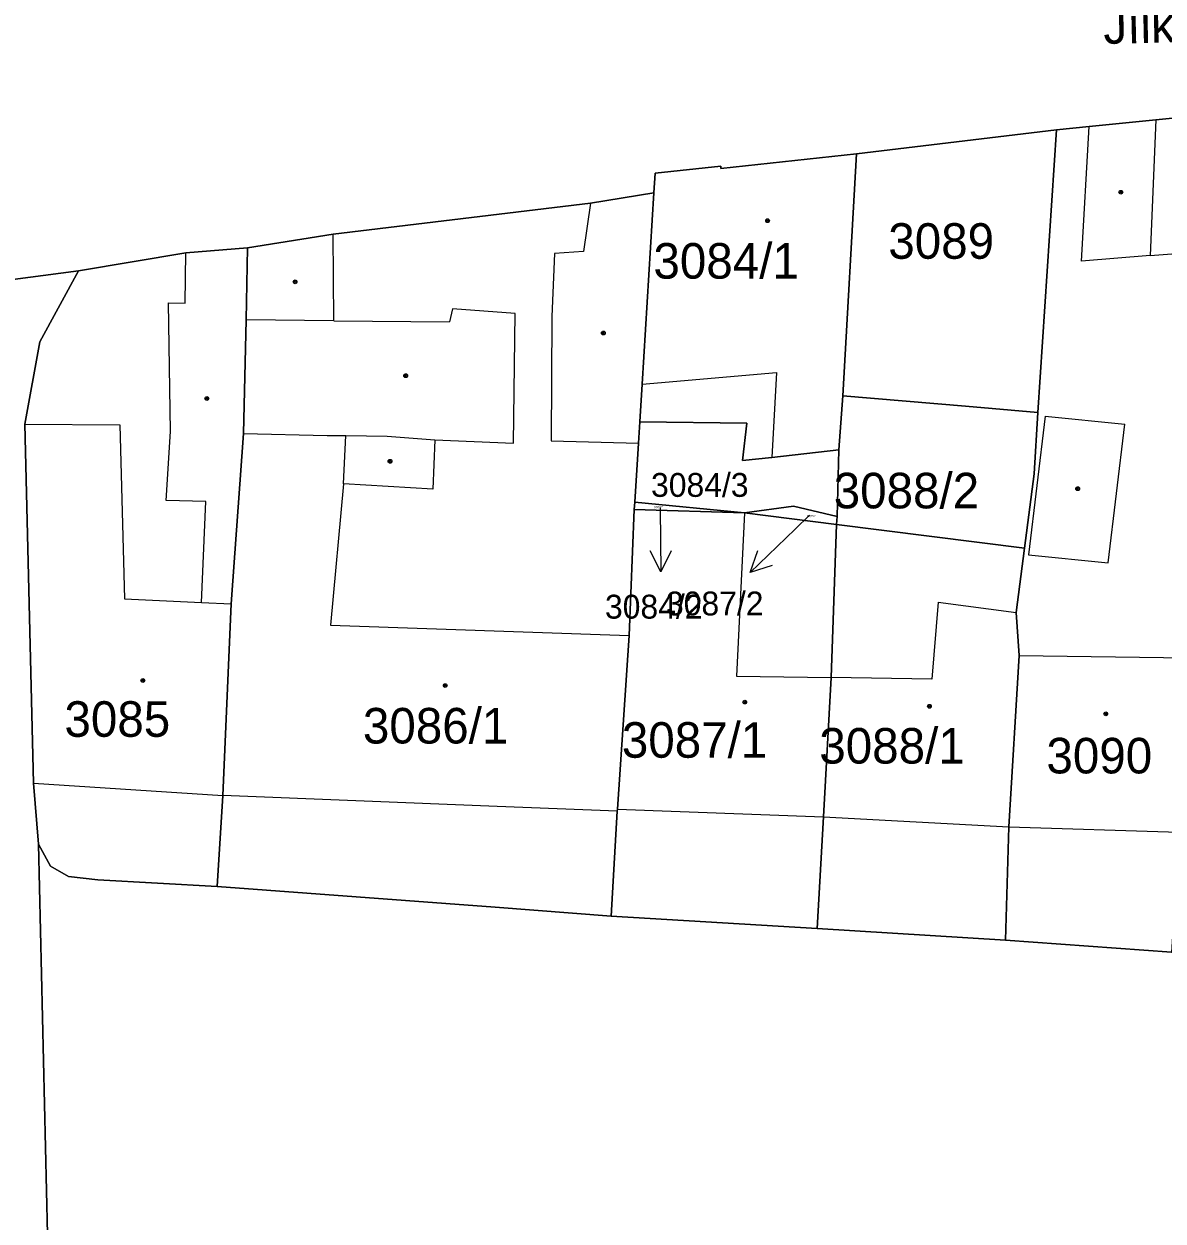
# Model space of a CAD drawing. Extents: x -596233 to -595156, y -1161235 to -1159375.
# Drawn here: x -595617.7 to -595563.3, y -1160940.7 to -1160883.5 of the extents above; entities that cross this region are included whole.
import ezdxf

# ---------------------------------------------------------------- set-up
doc = ezdxf.new("R2010")
doc.units = 0
for name, color, linetype in [('KN_CAR_KR', 7, 'Continuous'), ('KN_KULTURY', 7, 'Continuous'), ('KN_PARC_CIS_POM', 7, 'Continuous'), ('KN_PARC_CIS_POZ', 7, 'Continuous'), ('KN_PARC_CIS_STAV', 7, 'Continuous'), ('KN_PARC_PLOCHA', 7, 'Continuous'), ('KN_ULICE', 7, 'Continuous'), ('PARC_C_SIPKA', 7, 'Continuous'), ('parcely_l', 7, 'Continuous')]:
    doc.layers.add(name, color=color, linetype=linetype)

msp = doc.modelspace()

# ---------------------------------------------------------------- linework, layer by layer
at = {"layer": 'KN_CAR_KR'}
for points in [[(-595563.63, -1160888.1), (-595563.89, -1160894.59)], [(-595567.18, -1160894.85), (-595566.82, -1160888.42)], [(-595590.66, -1160892.08), (-595590.99, -1160894.4)], [(-595602.92, -1160897.71), (-595602.96, -1160893.57)], [(-595610.03, -1160896.86), (-595610, -1160894.45)], [(-595592.38, -1160894.48), (-595592.51, -1160897.5)], [(-595590.99, -1160894.4), (-595592.38, -1160894.48)], [(-595563.89, -1160894.59), (-595560.8, -1160894.35)], [(-595563.89, -1160894.59), (-595567.18, -1160894.85)], [(-595610.73, -1160902.99), (-595610.83, -1160896.85)], [(-595610.83, -1160896.85), (-595610.03, -1160896.86)], [(-595597.26, -1160897.14), (-595597.4, -1160897.76)], [(-595594.26, -1160897.35), (-595597.26, -1160897.14)], [(-595594.34, -1160903.55), (-595594.26, -1160897.35)], [(-595602.92, -1160897.71), (-595607.12, -1160897.66)], [(-595602.92, -1160897.71), (-595597.4, -1160897.76)], [(-595592.51, -1160897.5), (-595592.54, -1160903.44)], [(-595588.19, -1160900.74), (-595581.77, -1160900.17)], [(-595581.77, -1160900.17), (-595581.99, -1160904.24)], [(-595568.92, -1160902.27), (-595569.72, -1160908.89)], [(-595568.92, -1160902.27), (-595565.1, -1160902.64)], [(-595617.7, -1160902.65), (-595613.16, -1160902.67)], [(-595613.16, -1160902.67), (-595612.93, -1160911)], [(-595610.95, -1160906.29), (-595610.73, -1160902.99)], [(-595607.24, -1160903.09), (-595603.25, -1160903.18)], [(-595565.9, -1160909.27), (-595565.1, -1160902.64)], [(-595603.25, -1160903.18), (-595602.36, -1160903.19)], [(-595602.46, -1160905.5), (-595602.36, -1160903.19)], [(-595602.36, -1160903.19), (-595600.37, -1160903.22)], [(-595600.37, -1160903.22), (-595598.1, -1160903.4)], [(-595598.1, -1160903.4), (-595598.19, -1160905.75)], [(-595598.1, -1160903.4), (-595594.34, -1160903.55)], [(-595592.54, -1160903.44), (-595588.36, -1160903.56)], [(-595602.46, -1160905.5), (-595603.08, -1160912.26)], [(-595598.19, -1160905.75), (-595602.46, -1160905.5)], [(-595609.04, -1160906.34), (-595610.95, -1160906.29)], [(-595609.26, -1160911.17), (-595609.04, -1160906.34)], [(-595583.3, -1160906.89), (-595583.68, -1160914.69)], [(-595569.72, -1160908.89), (-595565.9, -1160909.27)], [(-595612.93, -1160911), (-595609.26, -1160911.17)], [(-595609.26, -1160911.17), (-595607.83, -1160911.24)], [(-595574.03, -1160911.16), (-595574.33, -1160914.84)], [(-595574.03, -1160911.16), (-595570.3, -1160911.64)], [(-595603.08, -1160912.26), (-595588.81, -1160912.74)], [(-595570.16, -1160913.7), (-595562.11, -1160913.81)], [(-595583.68, -1160914.69), (-595579.15, -1160914.76)], [(-595574.33, -1160914.84), (-595579.15, -1160914.76)], [(-595617.29, -1160919.81), (-595608.24, -1160920.4)], [(-595595.12, -1160920.92), (-595608.24, -1160920.4)], [(-595589.38, -1160921.15), (-595595.12, -1160920.92)], [(-595589.37, -1160921.05), (-595579.52, -1160921.41)], [(-595579.52, -1160921.41), (-595570.65, -1160921.89)], [(-595570.65, -1160921.89), (-595562.51, -1160922.15)]]:
    msp.add_lwpolyline(points, dxfattribs=at)
at = {"layer": 'KN_KULTURY'}
for centre, radius in [((-595565.3, -1160891.56), 0.09), ((-595565.3, -1160891.56), 0.0398), ((-595582.19, -1160892.92), 0.09), ((-595582.19, -1160892.92), 0.0398), ((-595604.78, -1160895.84), 0.09), ((-595604.78, -1160895.84), 0.0398), ((-595590.04, -1160898.29), 0.09), ((-595590.04, -1160898.29), 0.0398), ((-595599.49, -1160900.33), 0.09), ((-595599.49, -1160900.33), 0.0398), ((-595609, -1160901.42), 0.09), ((-595609, -1160901.42), 0.0398), ((-595600.24, -1160904.42), 0.09), ((-595600.24, -1160904.42), 0.0398), ((-595567.36, -1160905.73), 0.09), ((-595567.36, -1160905.73), 0.0398), ((-595612.06, -1160914.9), 0.09), ((-595612.06, -1160914.9), 0.0398), ((-595597.6, -1160915.14), 0.09), ((-595597.6, -1160915.14), 0.0398), ((-595583.28, -1160915.93), 0.09), ((-595583.28, -1160915.93), 0.0398), ((-595574.45, -1160916.13), 0.09), ((-595574.45, -1160916.13), 0.0398), ((-595566.02, -1160916.49), 0.09), ((-595566.02, -1160916.49), 0.0398)]:
    msp.add_circle(centre, radius, dxfattribs=at)
at = {"layer": 'KN_PARC_PLOCHA'}
for points in [[(-595560.43, -1160887.78), (-595563.63, -1160888.1), (-595566.82, -1160888.42), (-595568.37, -1160888.58), (-595577.93, -1160889.73), (-595584.43, -1160890.42), (-595584.43, -1160890.31), (-595587.57, -1160890.64), (-595587.63, -1160891.58), (-595590.66, -1160892.08), (-595602.96, -1160893.57), (-595607.05, -1160894.21), (-595610, -1160894.45), (-595615.14, -1160895.31), (-595631.7, -1160897.5)], [(-595631.7, -1160897.5), (-595615.14, -1160895.31), (-595616.98, -1160898.71), (-595617.7, -1160902.65), (-595617.29, -1160919.81), (-595617.05, -1160922.72), (-595616.62, -1160941.37), (-595616.22, -1160946.87), (-595615.26, -1160961.87), (-595614.82, -1160968.76), (-595614.38, -1160975.64), (-595613.94, -1160982.53), (-595617.11, -1160982.74), (-595617.35, -1160987.8), (-595617.56, -1160996.69), (-595615.79, -1161018.89), (-595611.5, -1161018.59), (-595609.88, -1161043.14), (-595608.93, -1161050.44), (-595606.83, -1161051.74), (-595620.07, -1161056.19)], [(-595616.62, -1160941.37), (-595617.05, -1160922.72), (-595616.48, -1160923.77), (-595615.61, -1160924.27), (-595614.21, -1160924.42), (-595608.5, -1160924.75), (-595595.22, -1160925.73), (-595589.67, -1160926.16), (-595579.82, -1160926.76), (-595570.81, -1160927.31), (-595562.88, -1160927.89), (-595551.46, -1160928.67), (-595543.1, -1160929.22), (-595527.5, -1160930.25), (-595519.67, -1160930.84), (-595512.22, -1160931.33), (-595504.18, -1160931.89), (-595500.69, -1160932.12), (-595499.12, -1160932.23), (-595491.47, -1160932.74)]]:
    msp.add_lwpolyline(points, dxfattribs=at)
for points in [[(-595561.16, -1160900.81), (-595561.26, -1160902.41), (-595561.43, -1160904.7), (-595561.69, -1160908.31), (-595561.79, -1160909.68), (-595561.89, -1160911.71), (-595562.11, -1160913.81), (-595562.51, -1160922.15), (-595562.88, -1160927.89), (-595570.81, -1160927.31), (-595570.65, -1160921.89), (-595570.16, -1160913.7), (-595570.3, -1160911.64), (-595569.91, -1160908.58), (-595569.45, -1160905.02), (-595569.26, -1160902.08), (-595568.37, -1160888.58), (-595566.82, -1160888.42), (-595563.63, -1160888.1), (-595560.43, -1160887.78), (-595560.8, -1160894.35), (-595560.89, -1160896.41)], [(-595569.26, -1160902.08), (-595572.72, -1160901.79), (-595578.59, -1160901.29), (-595577.93, -1160889.73), (-595568.37, -1160888.58)], [(-595578.59, -1160901.29), (-595578.78, -1160903.87), (-595581.99, -1160904.24), (-595583.38, -1160904.38), (-595583.18, -1160902.59), (-595588.3, -1160902.53), (-595588.19, -1160900.74), (-595587.63, -1160891.58), (-595587.57, -1160890.64), (-595584.43, -1160890.31), (-595584.43, -1160890.42), (-595577.93, -1160889.73)], [(-595588.3, -1160902.53), (-595588.36, -1160903.56), (-595588.54, -1160906.37), (-595588.56, -1160906.73), (-595588.81, -1160912.74), (-595589.37, -1160921.05), (-595589.38, -1160921.15), (-595589.67, -1160926.16), (-595595.22, -1160925.73), (-595608.5, -1160924.75), (-595608.24, -1160920.4), (-595607.83, -1160911.24), (-595607.24, -1160903.09), (-595607.12, -1160897.66), (-595607.05, -1160894.21), (-595602.96, -1160893.57), (-595590.66, -1160892.08), (-595587.63, -1160891.58), (-595588.19, -1160900.74)], [(-595608.5, -1160924.75), (-595614.21, -1160924.42), (-595615.61, -1160924.27), (-595616.48, -1160923.77), (-595617.05, -1160922.72), (-595617.29, -1160919.81), (-595617.7, -1160902.65), (-595616.98, -1160898.71), (-595615.14, -1160895.31), (-595610, -1160894.45), (-595607.05, -1160894.21), (-595607.12, -1160897.66), (-595607.24, -1160903.09), (-595607.83, -1160911.24), (-595608.24, -1160920.4)], [(-595569.26, -1160902.08), (-595569.45, -1160905.02), (-595569.91, -1160908.58), (-595578.9, -1160907.44), (-595578.86, -1160907.06), (-595578.78, -1160903.87), (-595578.59, -1160901.29), (-595572.72, -1160901.79)], [(-595578.78, -1160903.87), (-595578.86, -1160907.06), (-595580.95, -1160906.56), (-595583.3, -1160906.89), (-595588.54, -1160906.37), (-595588.36, -1160903.56), (-595588.3, -1160902.53), (-595583.18, -1160902.59), (-595583.38, -1160904.38), (-595581.99, -1160904.24)], [(-595583.3, -1160906.89), (-595588.56, -1160906.73), (-595588.54, -1160906.37)], [(-595578.86, -1160907.06), (-595578.9, -1160907.44), (-595583.3, -1160906.89), (-595580.95, -1160906.56)], [(-595583.3, -1160906.89), (-595578.9, -1160907.44), (-595579.15, -1160914.76), (-595579.52, -1160921.41), (-595579.82, -1160926.76), (-595589.67, -1160926.16), (-595589.38, -1160921.15), (-595589.37, -1160921.05), (-595588.81, -1160912.74), (-595588.56, -1160906.73)], [(-595569.91, -1160908.58), (-595570.3, -1160911.64), (-595570.16, -1160913.7), (-595570.65, -1160921.89), (-595570.81, -1160927.31), (-595579.82, -1160926.76), (-595579.52, -1160921.41), (-595579.15, -1160914.76), (-595578.9, -1160907.44)]]:
    msp.add_lwpolyline(points, close=True, dxfattribs=at)
at = {"layer": 'PARC_C_SIPKA'}
for points in [[(-595587.33, -1160906.66), (-595587.33, -1160906.7), (-595587.2905, -1160909.6997)], [(-595580.18, -1160906.99), (-595580.87, -1160907.66), (-595583.0289, -1160909.7431)], [(-595586.8037, -1160908.6932), (-595587.2905, -1160909.6997), (-595587.8036, -1160908.7064)], [(-595581.9621, -1160909.4085), (-595583.0289, -1160909.7431), (-595582.6564, -1160908.6889)]]:
    msp.add_lwpolyline(points, dxfattribs=at)
at = {"layer": 'parcely_l'}
for points in [[(-595560.43, -1160887.78), (-595563.63, -1160888.1), (-595566.82, -1160888.42), (-595568.37, -1160888.58)], [(-595568.37, -1160888.58), (-595577.93, -1160889.73)], [(-595569.26, -1160902.08), (-595568.37, -1160888.58)], [(-595577.93, -1160889.73), (-595584.43, -1160890.42), (-595584.43, -1160890.31), (-595587.57, -1160890.64), (-595587.63, -1160891.58)], [(-595578.59, -1160901.29), (-595577.93, -1160889.73)], [(-595587.63, -1160891.58), (-595590.66, -1160892.08), (-595602.96, -1160893.57), (-595607.05, -1160894.21)], [(-595587.63, -1160891.58), (-595588.19, -1160900.74), (-595588.3, -1160902.53)], [(-595607.05, -1160894.21), (-595610, -1160894.45), (-595615.14, -1160895.31)], [(-595607.05, -1160894.21), (-595607.12, -1160897.66), (-595607.24, -1160903.09), (-595607.83, -1160911.24), (-595608.24, -1160920.4), (-595608.5, -1160924.75)], [(-595615.14, -1160895.31), (-595631.7, -1160897.5)], [(-595617.05, -1160922.72), (-595617.29, -1160919.81), (-595617.7, -1160902.65), (-595616.98, -1160898.71), (-595615.14, -1160895.31)], [(-595578.78, -1160903.87), (-595578.59, -1160901.29)], [(-595578.59, -1160901.29), (-595572.72, -1160901.79), (-595569.26, -1160902.08)], [(-595588.54, -1160906.37), (-595588.36, -1160903.56), (-595588.3, -1160902.53)], [(-595588.3, -1160902.53), (-595583.18, -1160902.59), (-595583.38, -1160904.38), (-595581.99, -1160904.24), (-595578.78, -1160903.87)], [(-595569.26, -1160902.08), (-595569.45, -1160905.02), (-595569.91, -1160908.58)], [(-595578.78, -1160903.87), (-595578.86, -1160907.06)], [(-595588.54, -1160906.37), (-595588.56, -1160906.73)], [(-595583.3, -1160906.89), (-595588.54, -1160906.37)], [(-595578.86, -1160907.06), (-595580.95, -1160906.56), (-595583.3, -1160906.89)], [(-595589.67, -1160926.16), (-595589.38, -1160921.15), (-595589.37, -1160921.05), (-595588.81, -1160912.74), (-595588.56, -1160906.73)], [(-595588.56, -1160906.73), (-595583.3, -1160906.89)], [(-595583.3, -1160906.89), (-595578.9, -1160907.44)], [(-595578.9, -1160907.44), (-595578.86, -1160907.06)], [(-595578.9, -1160907.44), (-595579.15, -1160914.76), (-595579.52, -1160921.41), (-595579.82, -1160926.76)], [(-595569.91, -1160908.58), (-595578.9, -1160907.44)], [(-595570.81, -1160927.31), (-595570.65, -1160921.89), (-595570.16, -1160913.7), (-595570.3, -1160911.64), (-595569.91, -1160908.58)], [(-595616.62, -1160941.37), (-595617.05, -1160922.72)], [(-595617.05, -1160922.72), (-595616.48, -1160923.77), (-595615.61, -1160924.27), (-595614.21, -1160924.42), (-595608.5, -1160924.75)], [(-595608.5, -1160924.75), (-595595.22, -1160925.73), (-595589.67, -1160926.16)], [(-595589.67, -1160926.16), (-595579.82, -1160926.76)], [(-595579.82, -1160926.76), (-595570.81, -1160927.31)], [(-595570.81, -1160927.31), (-595562.88, -1160927.89)]]:
    msp.add_lwpolyline(points, dxfattribs=at)

# ---------------------------------------------------------------- texts
at = {"layer": 'KN_PARC_CIS_POM'}
for s, p in [('3084/2', (-595587.6133, -1160906.66)), ('3087/2', (-595580.3133, -1160907.09))]:
    msp.add_text(s, height=0.1, dxfattribs=at).set_placement(p)
at = {"layer": 'KN_PARC_CIS_POZ'}
for s, height, p in [('3089', 1.7, (-595576.4166, -1160894.74)), ('3084/3', 1.14, (-595587.76, -1160906.12)), ('3088/2', 1.7, (-595579.0266, -1160906.67)), ('3084/2', 1.14, (-595589.9634, -1160911.9398)), ('3087/2', 1.14, (-595587.0468, -1160911.7872))]:
    msp.add_text(s, height=height, dxfattribs=at).set_placement(p)
at = {"layer": 'KN_PARC_CIS_STAV'}
for s, p in [('3084/1', (-595587.6466, -1160895.69)), ('3085', (-595615.8066, -1160917.59)), ('3086/1', (-595601.5366, -1160917.91)), ('3087/1', (-595589.1566, -1160918.59)), ('3088/1', (-595579.7166, -1160918.87)), ('3090', (-595568.8566, -1160919.34))]:
    msp.add_text(s, height=1.7, dxfattribs=at).set_placement(p)
at = {"layer": 'KN_ULICE'}
msp.add_text('Jílkova', height=1.7, rotation=1.32129, dxfattribs=at).set_placement((-595566.1151, -1160884.4707))

doc.saveas('drawing.dxf')
